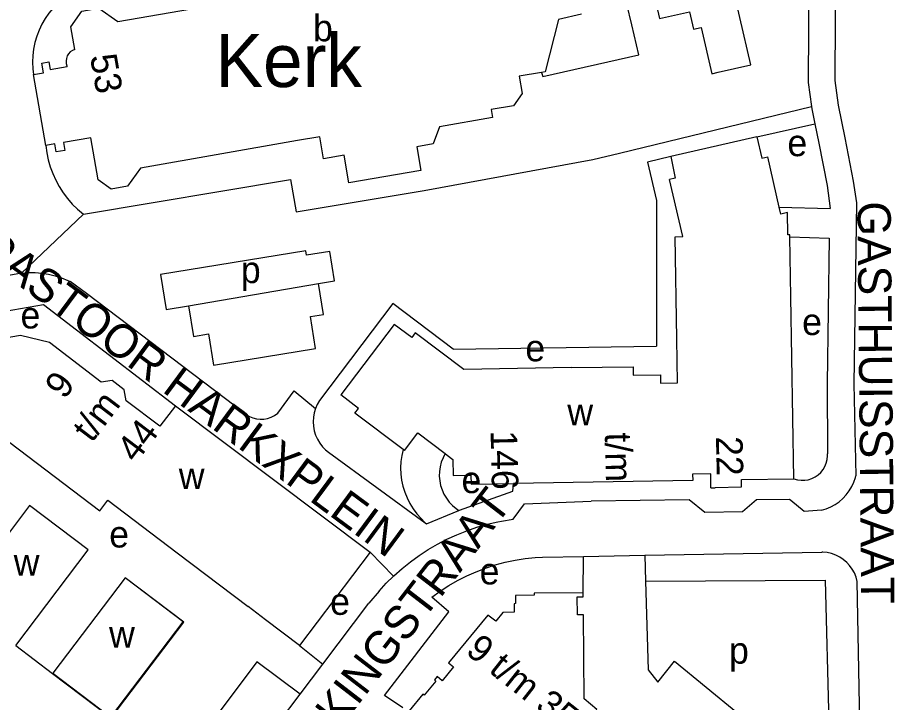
# Model space of a CAD drawing. Extents: x 161141 to 163125, y 381621 to 383200.
# Drawn here: x 161962.7 to 162094.5, y 382227.5 to 382330.5 of the extents above; entities that cross this region are included whole.
import ezdxf

# ---------------------------------------------------------------- set-up
doc = ezdxf.new("R2010")
doc.units = 0
for name, color, linetype in [('BLT_Basislijn', 7, 'Continuous'), ('BLT_Bebouwing', 7, 'Continuous'), ('BLT_Bebouwing_beschrifting', 7, 'Continuous'), ('BLT_Centroide', 7, 'Continuous'), ('BLT_Huisnummer_reeks', 7, 'Continuous'), ('BLT_Onderverdeling_panden', 7, 'Continuous'), ('BLT_Straatnaam', 7, 'Continuous'), ('BLT_Vlakafsluiter', 7, 'Continuous')]:
    doc.layers.add(name, color=color, linetype=linetype)

msp = doc.modelspace()

# ---------------------------------------------------------------- linework, layer by layer
at = {"layer": 'BLT_Basislijn'}
for p, q in [((162053.18, 382310.08), (162082.07, 382317.09)), ((162082.07, 382317.09), (162082.11, 382316.77)), ((162082.11, 382316.77), (162082.57, 382314.51)), ((162073.86, 382312.55), (162082.57, 382314.51)), ((162004.62, 382301.27), (162023.83, 382304.48)), ((162077.21, 382301.94), (162084.88, 382301.74)), ((162078.81, 382297.48), (162084.72, 382297.31)), ((162084.72, 382297.31), (162084.43, 382275.44)), ((161963.33, 382292.05), (161960.87, 382291.6)), ((161988.43, 382287.13), (162007.97, 382290.48)), ((161941.81, 382283.04), (161966.62, 382287.31)), ((161966.62, 382287.31), (161986.45, 382272.09)), ((162028.21, 382280.63), (162058.74, 382281.05)), ((162084.43, 382275.44), (162084.46, 382264.89)), ((162088.43, 382275.39), (162088.7, 382261.54)), ((162009.45, 382265.1), (162023.99, 382254.47)), ((162015.72, 382250.07), (162019.23, 382246.47)), ((162041.62, 382249.35), (162047.81, 382249.45)), ((162047.74, 382243.97), (162047.81, 382249.45)), ((162047.81, 382249.45), (162057.01, 382249.61)), ((162057.01, 382249.61), (162083.62, 382250.08)), ((162057.01, 382249.61), (162057.12, 382245.71)), ((162057.12, 382245.71), (162084.12, 382245.88)), ((162084.12, 382245.88), (162084.87, 382217.44)), ((162089.48, 382217.53), (162088.92, 382245.69)), ((162017.05, 382244.22), (162015.51, 382242.41)), ((162008.61, 382233.26), (162015.51, 382242.41)), ((161962.44, 382236.04), (161967.99, 382231.82)), ((162005.08, 382236.06), (162008.61, 382233.26)), ((162005.18, 382228.73), (162008.61, 382233.26)), ((161993.47, 382213.21), (162005.18, 382228.73))]:
    msp.add_line(p, q, dxfattribs=at)
for points in [[(162081.74, 382353.4), (162081.57, 382320.73), (162082.07, 382317.09)], [(162085.72, 382348.71), (162085.57, 382320.99), (162086.08, 382317.31)], [(161972.01, 382334.85), (161971.13, 382334.39), (161970.29, 382333.87), (161969.5, 382333.28), (161968.76, 382332.62), (161968.07, 382331.91), (161967.44, 382331.15), (161966.88, 382330.33), (161966.38, 382329.48), (161965.95, 382328.59), (161965.6, 382327.66), (161965.32, 382326.71), (161965.12, 382325.74), (161965, 382324.76), (161964.96, 382323.77), (161965, 382322.78), (161965.1, 382321.93)], [(162086.08, 382317.31), (162087.08, 382312.37), (162088.34, 382305.86), (162088.8, 382302.61), (162088.43, 382275.39)], [(162082.57, 382314.51), (162083.15, 382311.59), (162084.4, 382305.2), (162084.88, 382301.74)], [(161966.96, 382311.25), (161967.11, 382310.16), (161967.33, 382309.09), (161967.63, 382308.04), (161968.01, 382307.01), (161968.46, 382306.01), (161968.98, 382305.05), (161969.58, 382304.12), (161970.23, 382303.25), (161970.95, 382302.42), (161971.73, 382301.65), (161972.62, 382300.89)], [(162023.83, 382304.48), (162049.18, 382309.11), (162053.18, 382310.08)], [(162060.89, 382309.56), (162057.4, 382308.75), (162058.75, 382302.95), (162058.74, 382281.05)], [(161972.62, 382300.89), (162003.77, 382306.11), (162004.62, 382301.27)], [(162009.65, 382295.32), (162006.14, 382294.74), (162006.03, 382295.42), (161984.21, 382291.85), (161985.07, 382286.59), (161988.43, 382287.13)], [(162007.97, 382290.48), (162010.38, 382290.88), (162009.65, 382295.32)], [(161963.33, 382292.05), (161964.34, 382292.14), (161965.36, 382292.14), (161966.38, 382292.06), (161967.39, 382291.9), (161968.38, 382291.66), (161969.35, 382291.35), (161970.29, 382290.96), (161970.65, 382290.79)], [(161997.1, 382270.77), (161973.1, 382288.97), (161970.65, 382290.79)], [(161988.43, 382287.13), (161989.18, 382282.53), (161991.41, 382282.89), (161992.18, 382278.18), (162007.53, 382280.69), (162006.75, 382285.51), (162008.73, 382285.84), (162007.97, 382290.48)], [(162028.21, 382280.63), (162019.11, 382287.49), (162008.11, 382272.9)], [(162001.84, 382270.98), (162004.32, 382274.32), (162007.51, 382271.71)], [(162007.51, 382271.71), (162007.31, 382271.03), (162007.19, 382270.36), (162007.15, 382269.68), (162007.2, 382269.01), (162007.32, 382268.34), (162007.52, 382267.69), (162007.79, 382267.06), (162008.14, 382266.48), (162008.55, 382265.94), (162009.02, 382265.45), (162009.45, 382265.1)], [(162008.11, 382272.9), (162007.77, 382272.31), (162007.51, 382271.71)], [(161997.1, 382270.77), (161997.58, 382270.48), (161998.1, 382270.27), (161998.64, 382270.13), (161999.2, 382270.08), (161999.76, 382270.1), (162000.31, 382270.2), (162000.84, 382270.38), (162001.34, 382270.63), (162001.84, 382270.98)], [(162020.66, 382265.53), (162020.46, 382264.62), (162020.33, 382263.7), (162020.29, 382262.77), (162020.33, 382261.83), (162020.45, 382260.91), (162020.64, 382260), (162020.91, 382259.1), (162021.26, 382258.24), (162021.68, 382257.41), (162022.18, 382256.61), (162022.73, 382255.86), (162023.35, 382255.17), (162023.99, 382254.47)], [(162026.99, 382264.91), (162026.67, 382264.28), (162026.41, 382263.62), (162026.23, 382262.93), (162026.13, 382262.23), (162026.11, 382261.52), (162026.17, 382260.82), (162026.3, 382260.12), (162026.52, 382259.44), (162026.81, 382258.8), (162027.17, 382258.19), (162027.6, 382257.62), (162028.08, 382257.11), (162028.63, 382256.65), (162029.04, 382256.37)], [(162079.41, 382261.11), (162079.94, 382260.96), (162080.48, 382260.89), (162081.03, 382260.9), (162081.57, 382260.98), (162082.09, 382261.15), (162082.59, 382261.39), (162083.04, 382261.69), (162083.44, 382262.07), (162083.79, 382262.49), (162084.07, 382262.96), (162084.28, 382263.47), (162084.41, 382264), (162084.46, 382264.55), (162084.46, 382264.89)], [(162083.54, 382256.4), (162084.25, 382256.61), (162084.94, 382256.89), (162085.6, 382257.25), (162086.21, 382257.67), (162086.77, 382258.16), (162087.28, 382258.71), (162087.73, 382259.31), (162088.11, 382259.95), (162088.42, 382260.63), (162088.65, 382261.33), (162088.7, 382261.54)], [(162029.04, 382256.37), (162029.15, 382256.42), (162037.18, 382259.24), (162037.27, 382260.41)], [(162035.48, 382254.75), (162037.2, 382255.02), (162038.91, 382257.37), (162048.94, 382257.74)], [(162083.54, 382256.4), (162080.93, 382256.21), (162078.95, 382257.84), (162078.76, 382258.02), (162073.79, 382257.93), (162071.71, 382256.12), (162066.02, 382256.03), (162063.67, 382257.93), (162048.94, 382257.74)], [(162023.99, 382254.47), (162024.18, 382254.34), (162029.04, 382256.37)], [(162019.23, 382246.47), (162019.3, 382246.54), (162020.51, 382247.62), (162021.77, 382248.63), (162023.08, 382249.58), (162024.44, 382250.46), (162025.83, 382251.28), (162027.27, 382252.02), (162028.74, 382252.69), (162030.24, 382253.29), (162031.77, 382253.82), (162033.33, 382254.27), (162034.9, 382254.64), (162035.48, 382254.75)], [(162025.01, 382243.32), (162026.25, 382244.22), (162027.54, 382245.05), (162028.86, 382245.82), (162030.23, 382246.51), (162031.63, 382247.14), (162033.06, 382247.69), (162034.52, 382248.16), (162036, 382248.56), (162037.5, 382248.88), (162039.02, 382249.12), (162040.54, 382249.28), (162041.62, 382249.35)], [(162088.92, 382245.69), (162088.75, 382246.33), (162088.5, 382246.95), (162088.18, 382247.53), (162087.79, 382248.06), (162087.35, 382248.55), (162086.84, 382248.98), (162086.29, 382249.34), (162085.7, 382249.64), (162085.07, 382249.86), (162084.43, 382250.01), (162083.77, 382250.07), (162083.62, 382250.08)], [(162017.05, 382244.22), (162018.15, 382245.41), (162019.23, 382246.47)], [(162057.12, 382245.71), (162057.51, 382232.36), (162058.97, 382230.53), (162061.47, 382233.7), (162075.73, 382221.94), (162071.94, 382217.2), (162084.87, 382217.44)], [(162020.62, 382226.69), (162017.88, 382228.52), (162027.56, 382241.12), (162025.01, 382243.32)], [(162005.18, 382228.73), (161998.7, 382233.61), (161986.74, 382217.64)]]:
    msp.add_lwpolyline(points, dxfattribs=at)
at = {"layer": 'BLT_Bebouwing'}
for p, q in [((161966.96, 382311.25), (161965.1, 382321.93)), ((162073.86, 382312.55), (162060.89, 382309.56)), ((162077.21, 382301.94), (162075.48, 382309.54)), ((162078.97, 382288.49), (162078.81, 382297.48)), ((162079.41, 382261.11), (162078.97, 382288.49)), ((161986.45, 382272.09), (162015.72, 382250.07)), ((162020.87, 382265.38), (162020.66, 382265.53)), ((162026.99, 382264.91), (162027.29, 382264.68)), ((162064.2, 382260.85), (162037.27, 382260.41)), ((161964.53, 382257.1), (161954.56, 382243.93)), ((162015.72, 382250.07), (162005.08, 382236.06)), ((161978.88, 382246.2), (161968.02, 382231.87)), ((161978.88, 382246.2), (161968.03, 382231.87)), ((161968.03, 382231.87), (161967.99, 382231.82)), ((161967.99, 382231.82), (161976.79, 382225.15)), ((161968.02, 382231.87), (161968.03, 382231.87))]:
    msp.add_line(p, q, dxfattribs=at)
for points in [[(162056.1, 382324.89), (162055.03, 382329.38), (162054.31, 382332.48), (162058.49, 382333.44), (162059.21, 382330.32), (162063.71, 382331.36), (162064.32, 382328.71), (162065.47, 382328.97), (162067.07, 382322.04), (162068.05, 382322.27), (162072.93, 382323.39), (162069.63, 382337.66), (162065.92, 382336.8), (162065.59, 382338.21), (162063.8, 382337.79), (162061.4, 382348.15), (162059.89, 382349.1), (162056.4, 382348.3), (162055.53, 382346.89), (162055.63, 382346.42), (162044.5, 382343.85)], [(161971.32, 382325.68), (161970.72, 382329.09), (161972.38, 382331.46), (161974.94, 382331.91), (161977.81, 382329.89), (162001.4, 382333.99), (162004.55, 382334.54), (162004.02, 382337.61), (162005.13, 382337.8), (162004.91, 382339.08), (162005.47, 382339.88), (162006.69, 382340.1), (162006.3, 382342.34), (162010.13, 382343), (162009.73, 382345.33)], [(161971.32, 382325.68), (161970.96, 382325.53), (161970.65, 382325.31), (161970.39, 382325.03), (161970.19, 382324.7), (161970.06, 382324.34), (161970.01, 382323.96), (161970.04, 382323.58), (161970.15, 382323.21), (161970.19, 382323.1)], [(162041.49, 382322.24), (162041.65, 382321.6), (162056.1, 382324.89)], [(161965.1, 382321.93), (161966.6, 382322.19), (161966.35, 382323.62)], [(161966.35, 382323.62), (161967.44, 382323.81), (161967.64, 382322.65), (161970.19, 382323.1)], [(162041.49, 382322.24), (162038.1, 382321.65), (162038.55, 382319.04), (162037.26, 382317.22), (162033.9, 382316.63), (162034.11, 382315.43), (162026.16, 382314.05), (162025.21, 382311.49), (162022.73, 382311.06), (162023.35, 382307.49), (162012.53, 382305.61), (162011.81, 382309.77), (162008.73, 382309.23), (162008.15, 382312.56), (162004.82, 382311.98), (161981.18, 382307.84), (161979.27, 382305.12), (161976.79, 382304.69), (161974.82, 382306.07), (161973.72, 382312.4), (161969.61, 382311.68), (161969.81, 382310.49), (161968.53, 382310.27)], [(162073.86, 382312.55), (162074.6, 382309.34), (162075.48, 382309.54)], [(161968.53, 382310.27), (161968.32, 382311.49), (161966.96, 382311.25)], [(162060.89, 382309.56), (162061.55, 382306.34), (162060.71, 382306.14)], [(162061.81, 382282.15), (162061.56, 382297.52), (162062.71, 382297.55), (162060.71, 382306.14)], [(162078.81, 382297.48), (162078.8, 382297.82), (162078.51, 382297.81), (162078.46, 382301.15), (162077.44, 382300.93), (162077.21, 382301.94)], [(162045.91, 382277.84), (162029.8, 382277.53), (162022.51, 382283.05), (162021.97, 382282.34), (162019.33, 382284.32), (162011.32, 382273.72)], [(161986.45, 382272.09), (161984.12, 382269.04), (161979.05, 382272.85), (161978.75, 382274.5), (161976.92, 382275.9), (161975.29, 382275.66), (161967.51, 382281.59), (161963.19, 382282.65), (161953.6, 382280.99), (161952.2, 382281.92), (161949.93, 382281.52), (161948.95, 382280.21), (161942.66, 382279.14)], [(162045.91, 382277.84), (162055.27, 382277.95), (162055.26, 382276.7), (162059.37, 382276.75), (162059.38, 382275.52), (162061.9, 382275.55), (162061.81, 382282.15)], [(162020.66, 382265.53), (162013.42, 382271), (162013.96, 382271.71), (162011.32, 382273.72)], [(162020.87, 382265.38), (162022.89, 382268.03), (162026.99, 382264.91)], [(161945.3, 382263.8), (161961.55, 382266.57), (161975.1, 382256.28), (161976.29, 382257.89), (161986.69, 382250), (161997.37, 382241.91)], [(162027.29, 382264.68), (162028.15, 382264.02), (162028.19, 382261.6), (162030.84, 382261.64), (162030.88, 382260.31), (162037.27, 382260.41)], [(162066.95, 382259.74), (162066.91, 382261.86), (162064.18, 382261.82), (162064.2, 382260.85)], [(162066.95, 382259.74), (162067.56, 382259.76), (162067.57, 382259.82), (162071.56, 382259.88), (162071.55, 382260.99), (162079.41, 382261.11)], [(161962.44, 382236.04), (161973.33, 382250.43), (161964.53, 382257.1)], [(161968.03, 382231.87), (161976.75, 382225.26), (161987.61, 382239.58), (161978.88, 382246.2)], [(161976.79, 382225.15), (161987.69, 382239.53), (161978.88, 382246.2)], [(162047.74, 382243.97), (162040.37, 382243.89), (162040.38, 382243.6), (162037.57, 382243.56), (162037.56, 382242.35), (162037.38, 382242.31), (162037.38, 382241.05), (162035.67, 382241.02), (162034.59, 382239.68), (162033.43, 382240.61), (162027.51, 382233.42), (162028.26, 382232.81), (162026.55, 382230.75), (162025.8, 382231.36), (162025.4, 382230.86), (162025.59, 382230.7), (162023.85, 382228.57), (162023.66, 382228.73), (162021.6, 382226.2)], [(162052.32, 382224.36), (162051.88, 382224.74), (162051.73, 382224.56), (162049.64, 382226.26), (162049.78, 382226.44), (162047.91, 382228), (162047.81, 382240.67), (162046.88, 382240.67), (162046.82, 382243.35), (162047.75, 382243.36), (162047.74, 382243.97)], [(162005.08, 382236.06), (162000, 382239.91), (161997.37, 382241.91)]]:
    msp.add_lwpolyline(points, dxfattribs=at)
at = {"layer": 'BLT_Onderverdeling_panden'}
msp.add_lwpolyline([(162047.47, 382330.98), (162044.02, 382330.18), (162042.01, 382322.33), (162041.49, 382322.24)], dxfattribs=at)
at = {"layer": 'BLT_Vlakafsluiter'}
msp.add_line((161972.62, 382300.89), (161963.33, 382292.05), dxfattribs=at)

# ---------------------------------------------------------------- texts
at = {"layer": 'BLT_Bebouwing_beschrifting'}
msp.add_text('Kerk', height=8, dxfattribs=at).set_placement((161992.49, 382320.03))
at = {"layer": 'BLT_Centroide'}
for s, p in [('b', (162007.14, 382326.91)), ('e', (162078.44, 382309.63)), ('p', (161996.29, 382290.55)), ('e', (161963.17, 382283.72)), ('e', (162080.65, 382282.73)), ('e', (162039.05, 382278.78)), ('w', (162045.36, 382269.17)), ('w', (161986.96, 382259.56)), ('e', (162029.45, 382258.96)), ('e', (161976.5, 382250.78)), ('w', (161962.15, 382246.56)), ('e', (162032.18, 382245.23)), ('e', (162009.7, 382240.65)), ('w', (161976.48, 382235.73)), ('p', (162069.66, 382233.31))]:
    msp.add_text(s, height=4, dxfattribs=at).set_placement(p)
at = {"layer": 'BLT_Huisnummer_reeks'}
for s, rotation, p in [('53', 279.9097, (161973.6, 382324.68)), ('9', 53.6169, (161969.77, 382272.92)), ('t/m', 52.776, (161973.88, 382266.41)), ('44', 52.776, (161980.52, 382263.35)), ('146', 271.3083, (162033.82, 382268.36)), ('t/m', 271.3083, (162050.99, 382268.02)), ('22', 271.3083, (162067.69, 382267.47)), ('9 t/m 35', 321.5549, (162029.9, 382234.93))]:
    msp.add_text(s, height=4, rotation=rotation, dxfattribs=at).set_placement(p)
at = {"layer": 'BLT_Straatnaam'}
for s, rotation, p in [('GASTHUISSTRAAT', 270.5503, (162088.95, 382302.82)), ('PASTOOR HARKXPLEIN', 323.4931, (161956.53, 382294.85)), ('PASTOOR SICKINGSTRAAT', 52.4062, (161983.2, 382187.13))]:
    msp.add_text(s, height=5, rotation=rotation, dxfattribs=at).set_placement(p)

doc.saveas('drawing.dxf')
